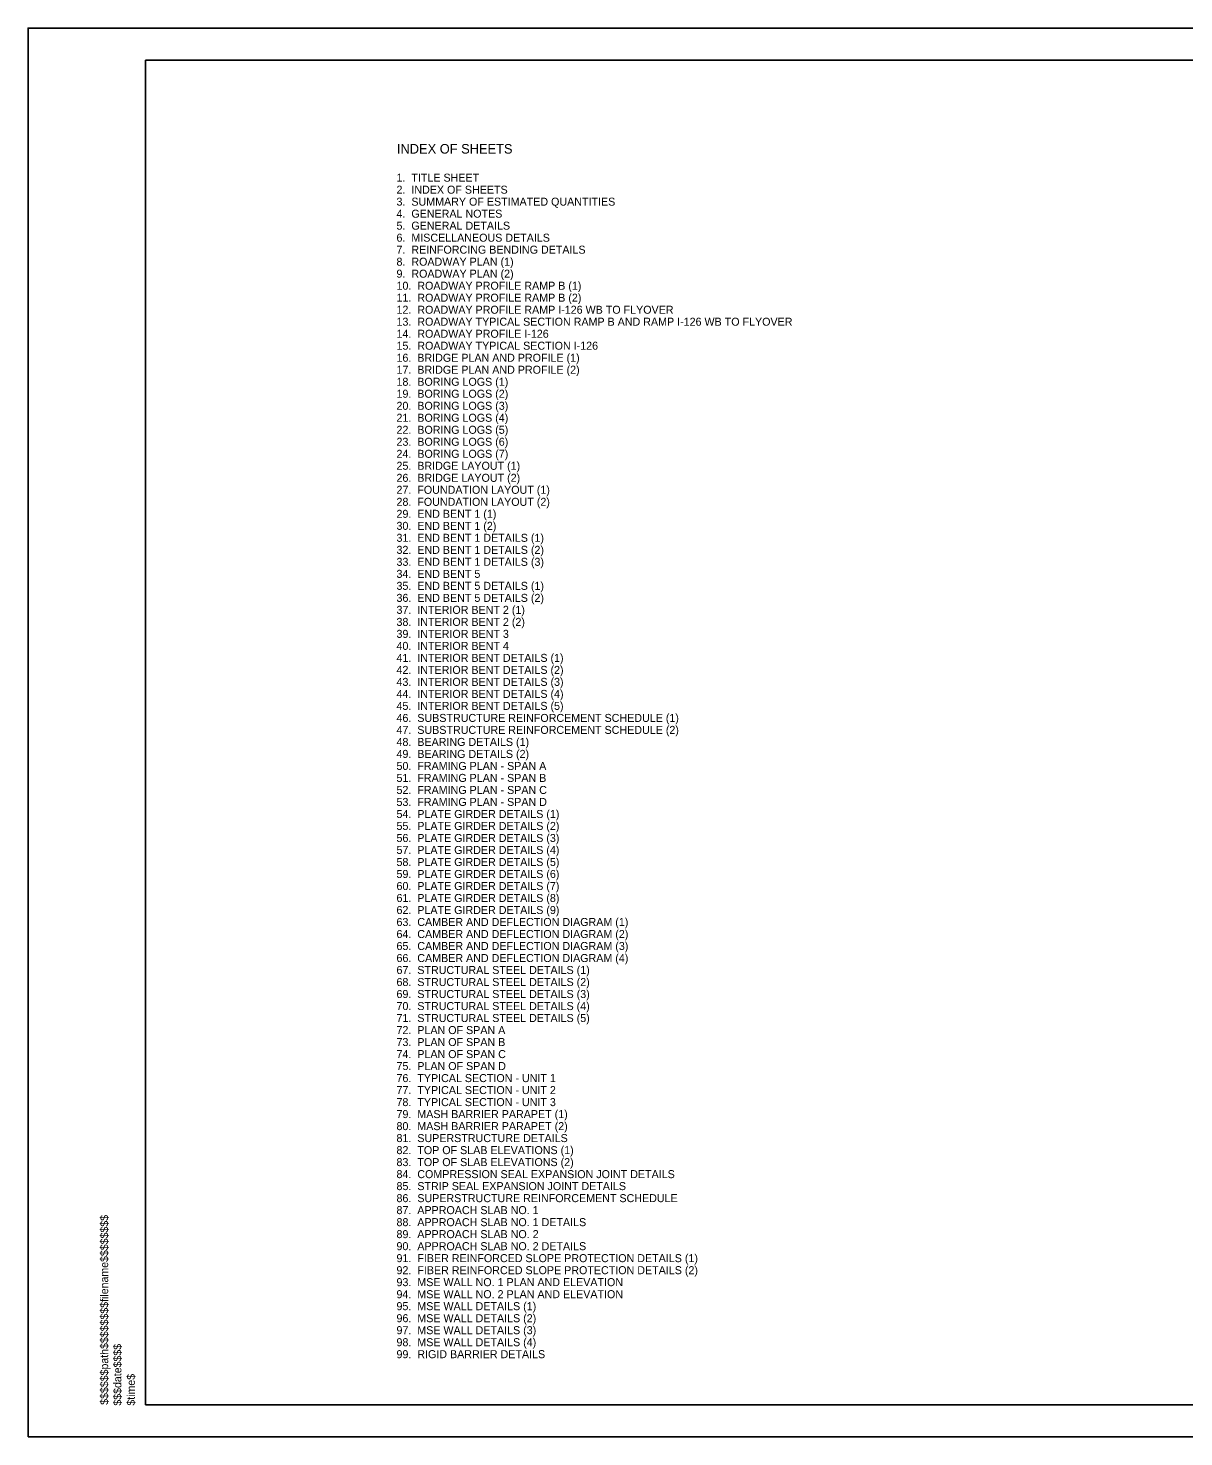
# Model space of a CAD drawing. Extents: x -125.5 to -89.4, y -5.1 to 16.9.
# Drawn here: x -125.53 to -107.48, y -5.07 to 16.93 of the extents above; entities that cross this region are included whole.
import ezdxf

# ---------------------------------------------------------------- set-up
doc = ezdxf.new("R2010")
doc.units = 0
for name, color, linetype in [('BR_AUTO DIMENSION', 7, 'Continuous'), ('BR_BORDER LINES', 7, 'Continuous'), ('BR_TEXT', 7, 'Continuous'), ('Level 31', 7, 'Continuous'), ('RD_SHT_ID', 7, 'Continuous')]:
    doc.layers.add(name, color=color, linetype=linetype)

msp = doc.modelspace()

# ---------------------------------------------------------------- linework, layer by layer
at = {"layer": 'BR_BORDER LINES'}
for p, q in [((-90.033, 16.434), (-123.699, 16.434)), ((-123.699, -4.566), (-123.699, 16.434)), ((-123.699, -4.566), (-90.033, -4.566))]:
    msp.add_line(p, q, dxfattribs=at)
at = {"layer": 'Level 31'}
msp.add_lwpolyline([(-125.533, -5.066), (-89.533, -5.066), (-89.533, 16.934), (-125.533, 16.934)], close=True, dxfattribs=at)

# ---------------------------------------------------------------- texts
at = {"layer": 'BR_AUTO DIMENSION'}
msp.add_text('INDEX OF SHEETS', height=0.15, dxfattribs=at).set_placement((-119.772, 14.975))
at = {"layer": 'BR_TEXT'}
for s, p in [('1.  TITLE SHEET', (-119.779, 14.537)), ('2.  INDEX OF SHEETS', (-119.779, 14.349)), ('4.  GENERAL NOTES', (-119.779, 13.974)), ('3.  SUMMARY OF ESTIMATED QUANTITIES', (-119.779, 14.162)), ('5.  GENERAL DETAILS', (-119.779, 13.787)), ('6.  MISCELLANEOUS DETAILS', (-119.779, 13.599)), ('7.  REINFORCING BENDING DETAILS  ', (-119.779, 13.412)), ('8.  ROADWAY PLAN (1)', (-119.779, 13.224)), ('9.  ROADWAY PLAN (2)', (-119.779, 13.037)), ('10.  ROADWAY PROFILE RAMP B (1)', (-119.779, 12.849)), ('11.  ROADWAY PROFILE RAMP B (2)', (-119.779, 12.662)), ('12.  ROADWAY PROFILE RAMP I-126 WB TO FLYOVER', (-119.779, 12.474)), ('13.  ROADWAY TYPICAL SECTION RAMP B AND RAMP I-126 WB TO FLYOVER', (-119.779, 12.287)), ('14.  ROADWAY PROFILE I-126', (-119.779, 12.099)), ('15.  ROADWAY TYPICAL SECTION I-126', (-119.779, 11.912)), ('16.  BRIDGE PLAN AND PROFILE (1)', (-119.779, 11.724)), ('17.  BRIDGE PLAN AND PROFILE (2)', (-119.779, 11.537)), ('18.  BORING LOGS (1)', (-119.779, 11.349)), ('19.  BORING LOGS (2)', (-119.779, 11.162)), ('20.  BORING LOGS (3)', (-119.779, 10.974)), ('21.  BORING LOGS (4)', (-119.779, 10.787)), ('22.  BORING LOGS (5)', (-119.779, 10.599)), ('23.  BORING LOGS (6)', (-119.779, 10.412)), ('24.  BORING LOGS (7)', (-119.779, 10.224)), ('25.  BRIDGE LAYOUT (1)', (-119.779, 10.037)), ('26.  BRIDGE LAYOUT (2)', (-119.779, 9.849)), ('27.  FOUNDATION LAYOUT (1)', (-119.779, 9.662)), ('28.  FOUNDATION LAYOUT (2)', (-119.779, 9.474)), ('29.  END BENT 1 (1)', (-119.779, 9.287)), ('30.  END BENT 1 (2)', (-119.779, 9.099)), ('31.  END BENT 1 DETAILS (1)', (-119.779, 8.912)), ('32.  END BENT 1 DETAILS (2)', (-119.779, 8.724)), ('33.  END BENT 1 DETAILS (3)', (-119.779, 8.537)), ('34.  END BENT 5', (-119.779, 8.349)), ('35.  END BENT 5 DETAILS (1)', (-119.779, 8.162)), ('36.  END BENT 5 DETAILS (2)', (-119.779, 7.974)), ('37.  INTERIOR BENT 2 (1)', (-119.779, 7.787)), ('38.  INTERIOR BENT 2 (2)', (-119.779, 7.599)), ('39.  INTERIOR BENT 3', (-119.779, 7.412)), ('40.  INTERIOR BENT 4', (-119.779, 7.224)), ('41.  INTERIOR BENT DETAILS (1)', (-119.779, 7.037)), ('42.  INTERIOR BENT DETAILS (2)', (-119.779, 6.849)), ('43.  INTERIOR BENT DETAILS (3)', (-119.779, 6.662)), ('44.  INTERIOR BENT DETAILS (4)', (-119.779, 6.474)), ('45.  INTERIOR BENT DETAILS (5)', (-119.779, 6.287)), ('46.  SUBSTRUCTURE REINFORCEMENT SCHEDULE (1)', (-119.779, 6.099)), ('47.  SUBSTRUCTURE REINFORCEMENT SCHEDULE (2)', (-119.779, 5.912)), ('48.  BEARING DETAILS (1)', (-119.779, 5.724)), ('49.  BEARING DETAILS (2)', (-119.779, 5.537)), ('50.  FRAMING PLAN - SPAN A', (-119.779, 5.349)), ('51.  FRAMING PLAN - SPAN B', (-119.779, 5.162)), ('52.  FRAMING PLAN - SPAN C', (-119.779, 4.974)), ('53.  FRAMING PLAN - SPAN D ', (-119.779, 4.787)), ('54.  PLATE GIRDER DETAILS (1) ', (-119.779, 4.599)), ('55.  PLATE GIRDER DETAILS (2)', (-119.779, 4.412)), ('56.  PLATE GIRDER DETAILS (3) ', (-119.779, 4.224)), ('57.  PLATE GIRDER DETAILS (4)', (-119.779, 4.037)), ('58.  PLATE GIRDER DETAILS (5) ', (-119.779, 3.849)), ('59.  PLATE GIRDER DETAILS (6)', (-119.779, 3.662)), ('60.  PLATE GIRDER DETAILS (7) ', (-119.779, 3.474)), ('61.  PLATE GIRDER DETAILS (8)', (-119.779, 3.287)), ('62.  PLATE GIRDER DETAILS (9) ', (-119.779, 3.099)), ('63.  CAMBER AND DEFLECTION DIAGRAM (1)', (-119.779, 2.912)), ('64.  CAMBER AND DEFLECTION DIAGRAM (2)', (-119.779, 2.724)), ('65.  CAMBER AND DEFLECTION DIAGRAM (3)', (-119.779, 2.537)), ('66.  CAMBER AND DEFLECTION DIAGRAM (4)', (-119.779, 2.349)), ('67.  STRUCTURAL STEEL DETAILS (1)', (-119.779, 2.162)), ('68.  STRUCTURAL STEEL DETAILS (2)', (-119.779, 1.974)), ('69.  STRUCTURAL STEEL DETAILS (3)', (-119.779, 1.787)), ('70.  STRUCTURAL STEEL DETAILS (4)', (-119.779, 1.599)), ('71.  STRUCTURAL STEEL DETAILS (5)', (-119.779, 1.412)), ('72.  PLAN OF SPAN A', (-119.779, 1.224)), ('73.  PLAN OF SPAN B', (-119.779, 1.037)), ('74.  PLAN OF SPAN C', (-119.779, 0.849)), ('75.  PLAN OF SPAN D ', (-119.779, 0.662)), ('76.  TYPICAL SECTION - UNIT 1', (-119.779, 0.474)), ('77.  TYPICAL SECTION - UNIT 2', (-119.779, 0.287)), ('78.  TYPICAL SECTION - UNIT 3', (-119.779, 0.099)), ('79.  MASH BARRIER PARAPET (1)', (-119.779, -0.088)), ('80.  MASH BARRIER PARAPET (2)', (-119.779, -0.276)), ('81.  SUPERSTRUCTURE DETAILS', (-119.779, -0.463)), ('82.  TOP OF SLAB ELEVATIONS (1)', (-119.779, -0.651)), ('83.  TOP OF SLAB ELEVATIONS (2)', (-119.779, -0.838)), ('84.  COMPRESSION SEAL EXPANSION JOINT DETAILS', (-119.779, -1.026)), ('85.  STRIP SEAL EXPANSION JOINT DETAILS', (-119.779, -1.213)), ('86.  SUPERSTRUCTURE REINFORCEMENT SCHEDULE', (-119.779, -1.401)), ('87.  APPROACH SLAB NO. 1', (-119.779, -1.588)), ('88.  APPROACH SLAB NO. 1 DETAILS', (-119.779, -1.776)), ('89.  APPROACH SLAB NO. 2', (-119.779, -1.963)), ('90.  APPROACH SLAB NO. 2 DETAILS', (-119.779, -2.151)), ('91.  FIBER REINFORCED SLOPE PROTECTION DETAILS (1)', (-119.779, -2.338)), ('92.  FIBER REINFORCED SLOPE PROTECTION DETAILS (2)', (-119.779, -2.526)), ('93.  MSE WALL NO. 1 PLAN AND ELEVATION', (-119.779, -2.713)), ('94.  MSE WALL NO. 2 PLAN AND ELEVATION', (-119.779, -2.901)), ('95.  MSE WALL DETAILS (1)', (-119.779, -3.088)), ('96.  MSE WALL DETAILS (2)', (-119.779, -3.276)), ('97.  MSE WALL DETAILS (3)', (-119.779, -3.463)), ('98.  MSE WALL DETAILS (4)', (-119.779, -3.651)), ('99.  RIGID BARRIER DETAILS', (-119.779, -3.838))]:
    msp.add_text(s, height=0.125, dxfattribs=at).set_placement(p)
at = {"layer": 'RD_SHT_ID'}
for s, height, p in [('$$$$$$path$$$$$$$$filename$$$$$$$$', 0.12347, (-124.283, -4.566)), ('$$$date$$$$', 0.12347, (-124.077, -4.579)), ('$time$', 0.1235, (-123.866, -4.579))]:
    msp.add_text(s, height=height, rotation=90, dxfattribs=at).set_placement(p)

doc.saveas('drawing.dxf')
